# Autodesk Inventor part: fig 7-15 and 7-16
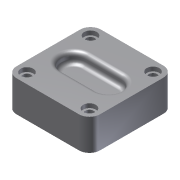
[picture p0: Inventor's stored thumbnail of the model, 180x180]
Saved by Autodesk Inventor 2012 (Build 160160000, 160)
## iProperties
Shininess: 77.0
Angle Display Precision: 2
Document Length Units: 11269
Document Angle Units: 11279
Document Time Units: 11290
Document Mass Units: 11283
Document Length Units Precision: 3
Document Angle Units Precision: 2
Created: 2001-12
Part Number: fig 7-15 and 7-16
Document SubType Name: Modeling
Designer: Renu Muthoo
Density: 1 g/cm^3
Material: Default
Density: 0.0
Volumn: 0.0
Area: 0.0
PropertySet Name: Model Information
Control State: 0
Master: False
Checked Out: False
Author: Renu Muthoo
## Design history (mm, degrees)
sketch "Sketch1"
  geometry: L1 (-20, 20)-(20, 20); L2 (20, 20)-(20, -20.5); L3 (20, -20.5)-(-20, -20.5); L4 (-20, -20.5)-(-20, 20); 1 further point
  constraints: 8 end point, 2 parallel, 1 horizontal, 1 perpendicular, 1 other
  dimensions: "d0" = 40 distance of L1.start L1.end; "d1" = 40.5 distance of L3.end L1.start; "d100" = 20 distance from line of L4 point (0, 0); "d101" = 20 distance from line of L1 point (0, 0)
extrude "Extrusion1" new body sketch "Sketch1" distance "d2" = 15; taper "d3" = 0 deg
workplane "Work Plane1"
workplane "Work Plane2"
workplane "Work Plane3"
workplane "Work Plane4"
fillet "Fillet1" dims "d32" = 5
hole "Hole3" diameter "d66" = 4; stored, may be unused: countersink angle "d70" = 90 deg, drill point angle "d72" = 118 deg; dims "d64" = 10, "d65" = 10, "d67" = 6, "d68" = 6, "d69" = 2, "d71" = 8
hole "Hole4" diameter "d75" = 4; stored, may be unused: countersink angle "d79" = 90 deg, drill point angle "d81" = 118 deg; dims "d73" = 10, "d74" = 10, "d76" = 6, "d77" = 6, "d78" = 2, "d80" = 8
hole "Hole5" diameter "d84" = 4; stored, may be unused: countersink angle "d88" = 90 deg, drill point angle "d90" = 118 deg; dims "d82" = 10, "d83" = 10, "d85" = 6, "d86" = 6, "d87" = 2, "d89" = 8
hole "Hole6" diameter "d93" = 4; stored, may be unused: countersink angle "d97" = 90 deg, drill point angle "d99" = 118 deg; dims "d91" = 10, "d92" = 10, "d94" = 6, "d95" = 6, "d96" = 2, "d98" = 8
fillet "Fillet2" dims "d61" = 2
body "Solid1"
sketch "Sketch8"
  geometry: L1 (-9.844, 1.64)-(1.983, -10.187); L2 (10.469, -1.701)-(-1.358, 10.126); A1 r 6 centre (-5.601, 5.883) between (-1.358, 10.126) and (-9.844, 1.64); A2 r 6 centre (6.226, -5.944) between (1.983, -10.187) and (10.469, -1.701)
  constraints: 4 end point, 4 point on circle, 4 tangent, 2 centre point, 1 parallel
  dimensions: "d29" = 6 radius of A2
extrude "Extrusion2" cut sketch "Sketch8" distance "d30" = 5; taper "d31" = 0 deg
